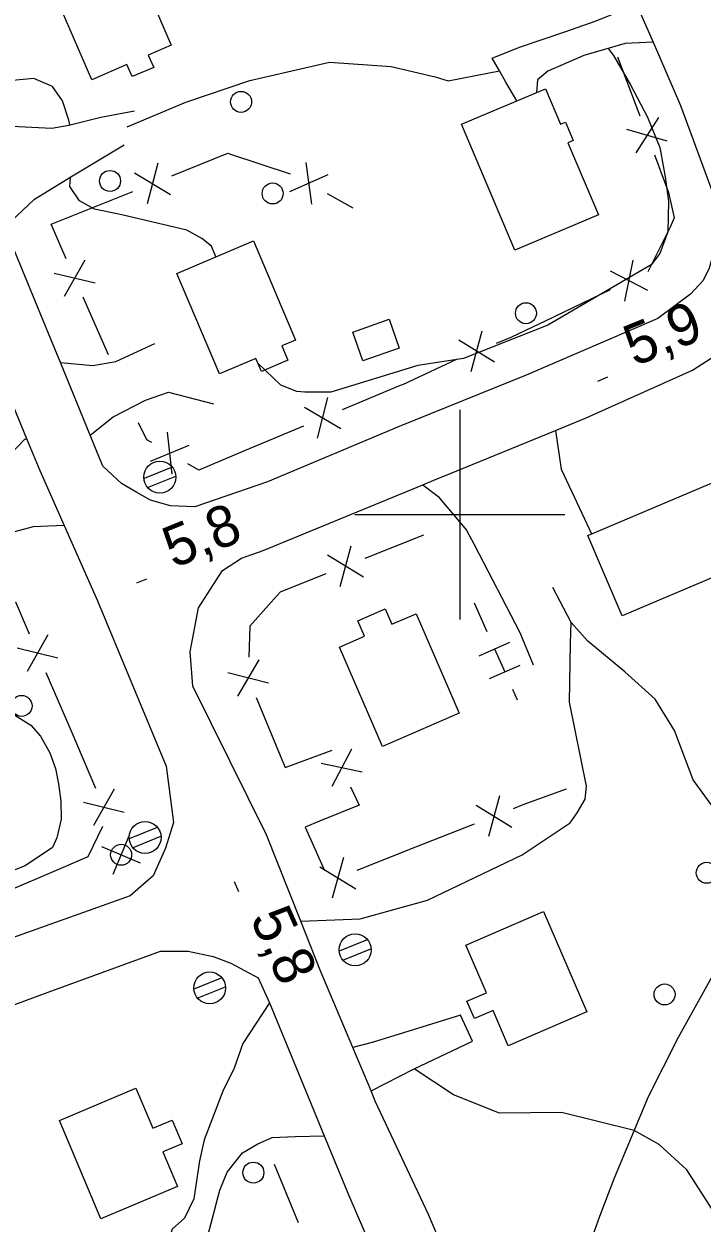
# Model space of a CAD drawing. Extents: x 362852 to 366875, y 5563573 to 5566479.
# Drawn here: x 364158.5 to 364223.1, y 5564732.5 to 5564846.8 of the extents above; entities that cross this region are included whole.
import ezdxf

# ---------------------------------------------------------------- set-up
doc = ezdxf.new("R2010")
doc.units = 0
for name, color, linetype in [('Niveau 19', 7, 'Continuous'), ('Niveau 2', 7, 'Continuous'), ('Niveau 21', 7, 'Continuous'), ('Niveau 22', 7, 'Continuous'), ('Niveau 3', 7, 'Continuous'), ('Niveau 31', 7, 'Continuous'), ('Niveau 36', 7, 'Continuous'), ('Niveau 37', 7, 'Continuous'), ('Niveau 61', 7, 'Continuous')]:
    doc.layers.add(name, color=color, linetype=linetype)

msp = doc.modelspace()

# ---------------------------------------------------------------- linework, layer by layer
at = {"layer": 'Niveau 19'}
for points in [[(364205.44, 5564839.42), (364204.39, 5564841.2), (364203.78, 5564842.29), (364203.1, 5564843.48), (364205.69, 5564844.54), (364210.02, 5564846), (364212.99, 5564847.04), (364215.14, 5564847.92), (364216.63, 5564849.16)], [(364218.42, 5564845.03), (364215.78, 5564844.88), (364211.84, 5564843.76), (364208.38, 5564842.27), (364207.41, 5564841.44), (364207.3, 5564840.21)], [(364152.13, 5564837.93), (364156.67, 5564837.06), (364161.12, 5564836.83), (364162.75, 5564837.12), (364165.8, 5564837.87), (364169, 5564838.49)], [(364156.64, 5564827.39), (364159.47, 5564830.05), (364163.11, 5564832.28), (364168.01, 5564835.22)], [(364161.94, 5564814.49), (364165.03, 5564814.2), (364167.21, 5564814.59), (364170.93, 5564816.3)], [(364164.77, 5564807.56), (364166.96, 5564809.32), (364170.06, 5564810.9), (364172.24, 5564811.67), (364176.54, 5564810.57)], [(364162.31, 5564798.95), (364159.34, 5564798.85), (364156.12, 5564797.97), (364153.67, 5564796.72), (364149.47, 5564794.19), (364146.59, 5564792.7), (364146.12, 5564793.54), (364145.48, 5564794.67), (364146.69, 5564796.98), (364146.53, 5564797.84), (364146.23, 5564799.34), (364149.87, 5564800.71), (364154.72, 5564803.87), (364157.16, 5564805.74), (364158.51, 5564807.17), (364158.71, 5564807.25)], [(364209.13, 5564808.03), (364209.68, 5564804.33), (364211.63, 5564800.15), (364212.56, 5564798.16)], [(364196.47, 5564802.84), (364197.91, 5564801.76), (364200.65, 5564798.52), (364201.37, 5564797.14), (364205.74, 5564788.78), (364207, 5564785.68)], [(364181.86, 5564753.49), (364179.34, 5564749.59), (364178.51, 5564747.26), (364177.41, 5564745.07), (364175.63, 5564740.42), (364175.19, 5564738.44), (364174.65, 5564734.8), (364173.78, 5564732.95), (364172.59, 5564731.91), (364171.97, 5564729.85), (364170.71, 5564728.96), (364170.89, 5564727.54), (364171.78, 5564726.1), (364172.84, 5564726.1), (364174.02, 5564726.71), (364175.31, 5564728.73), (364177.12, 5564735.62), (364177.84, 5564737.35), (364179.31, 5564739.19), (364180.77, 5564740.04), (364182.13, 5564740.66), (364184.33, 5564740.75), (364187.08, 5564740.82)], [(364191.55, 5564745.08), (364195.65, 5564747.19), (364201.21, 5564749.83), (364200.08, 5564752.29), (364194.63, 5564750.63), (364191.64, 5564749.71), (364189.81, 5564749.21)]]:
    msp.add_lwpolyline(points, dxfattribs=at)
at = {"layer": 'Niveau 2'}
for points in [[(364214.15, 5564844.42), (364214.64, 5564843.75), (364216.28, 5564840.94), (364217.9, 5564837.86), (364219.07, 5564834.98), (364219.58, 5564832.2), (364219.91, 5564829.85), (364219.84, 5564826.95), (364219.06, 5564824.89), (364218.25, 5564823.81), (364208.4, 5564818.04), (364200.36, 5564814.87), (364196.02, 5564814.21), (364187.71, 5564811.68), (364185.23, 5564811.66), (364184.46, 5564811.72), (364182.96, 5564812.35), (364180.75, 5564814.43), (364180.56, 5564814.89)], [(364162.85, 5564837.14), (364162.76, 5564837.58), (364162.13, 5564839.44), (364161.2, 5564840.8), (364159.4, 5564841.56), (364157.37, 5564841.35), (364156.15, 5564840.98), (364155.2, 5564839.96), (364154.48, 5564838.67), (364154.19, 5564837.53)], [(364176.75, 5564824.56), (364176.34, 5564825.58), (364175.42, 5564826.32), (364173.98, 5564827.1), (364167.79, 5564828.56), (364165.2, 5564829.11), (364163.77, 5564829.9), (364162.84, 5564831.26), (364162.91, 5564832.16)], [(364146.41, 5564777.11), (364147.11, 5564777.94), (364148.39, 5564779.09), (364150.82, 5564780.46), (364154.1, 5564781.86), (364155.22, 5564782.01), (364155.86, 5564781.96), (364157.1, 5564781.22), (364159.12, 5564779.93)], [(364159.12, 5564779.93), (364160.04, 5564778.88), (364160.93, 5564777.31), (364161.48, 5564775.8), (364161.76, 5564774.35), (364161.99, 5564772.71), (364162.01, 5564770.97), (364161.61, 5564769.19), (364161.18, 5564768.27), (364158.59, 5564766.53), (364152.47, 5564764.14), (364148.57, 5564764.41), (364147.66, 5564765.02)]]:
    msp.add_lwpolyline(points, dxfattribs=at)
at = {"layer": 'Niveau 21'}
for points in [[(364216.63, 5564849.16), (364218.42, 5564845.03), (364221.03, 5564838.99), (364224.78, 5564828.82), (364224.63, 5564826.58), (364223.77, 5564823.49), (364223.19, 5564822.32), (364221.98, 5564821.01), (364218.88, 5564818.68), (364206.32, 5564813.29), (364194.24, 5564808.41), (364181.67, 5564803.14), (364174.76, 5564800.75), (364172.42, 5564800.85), (364170.52, 5564801.38), (364169.24, 5564802.1), (364167.76, 5564802.98), (364165.97, 5564804.62), (364164.77, 5564807.56), (364161.94, 5564814.49), (364161.02, 5564816.73), (364156.64, 5564827.39)], [(364154.47, 5564817.47), (364158.71, 5564807.25), (364159.97, 5564804.22), (364162.31, 5564798.95), (364165.49, 5564791.79), (364172.02, 5564776.03), (364172.71, 5564770.65), (364171.95, 5564768.23), (364170.79, 5564765.57), (364168.58, 5564763.67), (364156.02, 5564759.21)], [(364202.8, 5564719.64), (364197.02, 5564733.32), (364191.95, 5564744.12), (364191.55, 5564745.08), (364189.81, 5564749.21), (364186.7, 5564756.59), (364184.85, 5564761.25), (364181.58, 5564769.49), (364174.55, 5564783.67), (364174.31, 5564786.93), (364175.1, 5564791.11), (364177.39, 5564794.66), (364179.21, 5564795.85), (364181.28, 5564796.57), (364196.47, 5564802.84), (364197.54, 5564803.29), (364199.19, 5564803.96), (364209.13, 5564808.03), (364212.05, 5564809.23), (364222.18, 5564813.75), (364226.74, 5564816.68)], [(364148.19, 5564749.85), (364160.77, 5564754.5), (364171.47, 5564758.39), (364174.11, 5564758.41), (364176.49, 5564757.89), (364178.18, 5564757.27), (364180.78, 5564755.85), (364181.86, 5564753.49), (364186.29, 5564742.74), (364187.08, 5564740.82), (364189.42, 5564735.12), (364193.71, 5564725.18)]]:
    msp.add_lwpolyline(points, dxfattribs=at)
at = {"layer": 'Niveau 22'}
for points in [[(364168.32, 5564836.96), (364173.9, 5564839.31), (364179.98, 5564841.36), (364187.58, 5564843.11), (364193.47, 5564842.71), (364197.67, 5564841.7), (364198.91, 5564841.33), (364203.78, 5564842.29)], [(364232.56, 5564769.27), (364228.13, 5564770.01), (364226.34, 5564770.52), (364224.48, 5564771.68), (364222.25, 5564774.74), (364220.47, 5564779.43), (364218.61, 5564782.4), (364215.74, 5564785.02), (364212.21, 5564787.94), (364210.62, 5564789.72), (364208.86, 5564793.04)], [(364206.94, 5564709.89), (364208.04, 5564715.36), (364210.03, 5564723.81), (364213.34, 5564733.15), (364214.75, 5564736.82), (364217.99, 5564744.55), (364220.85, 5564750.21), (364223.86, 5564755.63), (364228.21, 5564761.96), (364232.11, 5564768.28), (364232.56, 5564769.27), (364234.48, 5564773.48), (364235.31, 5564779.29), (364235.65, 5564787.33), (364236.12, 5564788.95), (364237.04, 5564790.75)], [(364184.85, 5564761.25), (364190.5, 5564761.5), (364196.93, 5564763.26), (364205.96, 5564767.57), (364210.51, 5564770.62), (364211.18, 5564771.58), (364211.95, 5564772.89), (364212.07, 5564774.12), (364210.47, 5564782.12), (364210.57, 5564787.76), (364210.62, 5564789.72)], [(364255.64, 5564707.29), (364252.39, 5564706.49), (364250.25, 5564706.24), (364248.51, 5564706.39), (364244.04, 5564707.61), (364242.18, 5564708.45), (364239.3, 5564710.87), (364235.19, 5564716.64), (364229.24, 5564724.72), (364226.9, 5564729.42), (364221.63, 5564737.58), (364218.99, 5564739.99), (364216.62, 5564741.3), (364209.7, 5564743.03), (364203.78, 5564742.97), (364199.39, 5564744.73), (364195.65, 5564747.19)]]:
    msp.add_lwpolyline(points, dxfattribs=at)
at = {"layer": 'Niveau 3'}
for p, q in [((364213.15, 5564812.73), (364214.11, 5564813.12)), ((364169.22, 5564793.5), (364170.18, 5564793.89)), ((364178.49, 5564765.03), (364178.92, 5564764.08))]:
    msp.add_line(p, q, dxfattribs=at)
at = {"layer": 'Niveau 31'}
for points in [[(364167.15, 5564857.11), (364172.49, 5564844.73), (364170.32, 5564843.79), (364170.83, 5564842.62), (364168.78, 5564841.74), (364168.28, 5564842.89), (364164.93, 5564841.44), (364159.58, 5564853.85), (364167.15, 5564857.11)], [(364205.25, 5564825.2), (364200.17, 5564837.19), (364208.16, 5564840.58), (364209.59, 5564837.2), (364210.07, 5564837.41), (364210.81, 5564835.65), (364210.3, 5564835.44), (364213.21, 5564828.57), (364205.25, 5564825.2)], [(364180.33, 5564826.08), (364184.36, 5564816.63), (364183.03, 5564816.07), (364183.61, 5564814.71), (364181.1, 5564813.64), (364180.57, 5564814.89), (364177.11, 5564813.42), (364173.04, 5564822.98), (364180.33, 5564826.08)], [(364189.8, 5564817.4), (364193.26, 5564818.63), (364194.24, 5564815.87), (364190.78, 5564814.64), (364189.8, 5564817.4)], [(364212.22, 5564798.01), (364224.67, 5564803.29), (364227.92, 5564795.63), (364215.47, 5564790.35), (364212.22, 5564798.01)], [(364195.86, 5564790.56), (364199.96, 5564781.08), (364192.63, 5564777.91), (364188.54, 5564787.38), (364190.92, 5564788.41), (364190.28, 5564789.89), (364192.88, 5564791.02), (364193.52, 5564789.55), (364195.86, 5564790.56)], [(364207.97, 5564762.19), (364212.1, 5564752.63), (364204.62, 5564749.39), (364203.17, 5564752.75), (364201.41, 5564751.99), (364200.69, 5564753.64), (364202.54, 5564754.44), (364200.57, 5564758.99), (364207.97, 5564762.19)], [(364165.81, 5564732.9), (364161.84, 5564742.28), (364169.14, 5564745.36), (364170.76, 5564741.53), (364172.59, 5564742.3), (364173.55, 5564740.05), (364171.71, 5564739.28), (364173.1, 5564735.98), (364165.81, 5564732.9)]]:
    msp.add_lwpolyline(points, dxfattribs=at)
at = {"layer": 'Niveau 36'}
for p, q in [((364172.59, 5564804.52), (364169.91, 5564803.43)), ((364170.25, 5564802.58), (364172.94, 5564803.67)), ((364166.96, 5564765.73), (364168.51, 5564769.4)), ((364171.16, 5564770.2), (364168.48, 5564769.11)), ((364168.82, 5564768.26), (364171.51, 5564769.35)), ((364169.57, 5564766.79), (364165.9, 5564768.34)), ((364191.19, 5564759.48), (364188.51, 5564758.39)), ((364188.85, 5564757.54), (364191.54, 5564758.63)), ((364177.33, 5564755.86), (364174.65, 5564754.77)), ((364174.99, 5564753.92), (364177.68, 5564755.01))]:
    msp.add_line(p, q, dxfattribs=at)
for centre, radius in [((364179.16, 5564839.33), 1), ((364166.67, 5564831.79), 1), ((364182.17, 5564830.6), 1), ((364206.31, 5564819.19), 1), ((364171.42, 5564803.57), 1.52), ((364158.24, 5564781.77), 1), ((364170.01, 5564769.24), 1.52), ((364167.73, 5564767.59), 1), ((364223.54, 5564765.87), 1), ((364190.03, 5564758.53), 1.52), ((364176.17, 5564754.9), 1.52), ((364219.52, 5564754.28), 1), ((364180.33, 5564737.3), 1)]:
    msp.add_circle(centre, radius, dxfattribs=at)
at = {"layer": 'Niveau 37'}
for p, q in [((364215.05, 5564843.63), (364217.16, 5564838.01)), ((364218.93, 5564837.83), (364216.78, 5564834.46)), ((364219.78, 5564835.58), (364215.94, 5564836.7)), ((364171.23, 5564833.48), (364170.2, 5564829.61)), ((364178.14, 5564834.36), (364183.83, 5564832.46)), ((364185.34, 5564833.54), (364185.88, 5564829.58)), ((364169, 5564832.58), (364172.42, 5564830.51)), ((364187.44, 5564832.37), (364183.78, 5564830.75)), ((364163.29, 5564828.57), (364168.86, 5564830.8)), ((364187.36, 5564830.59), (364189.8, 5564829.23)), ((364162.33, 5564820.8), (364164.3, 5564824.29)), ((364215.74, 5564820.33), (364216.52, 5564824.25)), ((364161.36, 5564823), (364165.26, 5564822.09)), ((364217.91, 5564821.37), (364214.36, 5564823.21)), ((364166.52, 5564815.22), (364164.11, 5564820.71)), ((364214.33, 5564821.42), (364208.92, 5564818.81)), ((364201.09, 5564813.65), (364202.14, 5564817.51)), ((364203.32, 5564814.54), (364199.91, 5564816.63)), ((364194.32, 5564812.29), (364188.79, 5564809.97)), ((364186.45, 5564807.27), (364187.43, 5564811.15)), ((364188.67, 5564808.19), (364185.22, 5564810.22)), ((364185.1, 5564808.43), (364179.56, 5564806.11)), ((364172.6, 5564803.87), (364172.15, 5564807.85)), ((364170.53, 5564805.08), (364174.22, 5564806.63)), ((364196.55, 5564798.03), (364190.97, 5564795.82)), ((364188.59, 5564793.16), (364189.64, 5564797.02)), ((364190.82, 5564794.04), (364187.41, 5564796.14)), ((364201.37, 5564791.6), (364202.59, 5564788.86)), ((364160.75, 5564788.53), (364158.76, 5564785.06)), ((364161.7, 5564786.33), (364157.81, 5564787.27)), ((364180.86, 5564786.15), (364178.82, 5564782.71)), ((364160.55, 5564784.96), (364162.92, 5564779.45)), ((364181.78, 5564783.94), (364177.9, 5564784.93)), ((364205.02, 5564783.37), (364205.48, 5564782.34)), ((364180.61, 5564782.58), (364182.9, 5564777.04)), ((364162.92, 5564779.45), (364165.29, 5564773.94)), ((364189.67, 5564777.64), (364187.8, 5564774.1)), ((364190.69, 5564775.46), (364186.78, 5564776.27)), ((364167.07, 5564773.84), (364165.08, 5564770.37)), ((364203.79, 5564773.2), (364202.73, 5564769.34)), ((364168.02, 5564771.63), (364164.13, 5564772.57)), ((364201.56, 5564772.32), (364204.96, 5564770.22)), ((364195.82, 5564768.33), (364201.4, 5564770.54)), ((364190.24, 5564766.13), (364195.82, 5564768.33)), ((364188.91, 5564767.32), (364187.85, 5564763.46)), ((364161.99, 5564766.29), (364156.48, 5564763.93)), ((364186.68, 5564766.43), (364190.09, 5564764.34)), ((364182.3, 5564738.1), (364184.61, 5564732.56))]:
    msp.add_line(p, q, dxfattribs=at)
for points in [[(364172.57, 5564832.29), (364177.91, 5564834.44), (364178.14, 5564834.36)], [(364218.56, 5564834.27), (364219.91, 5564830.68), (364220.38, 5564828.56)], [(364162.5, 5564824.38), (364161.06, 5564827.67), (364163.29, 5564828.57)], [(364220.38, 5564828.56), (364220.44, 5564828.29), (364220.06, 5564827.38), (364217.93, 5564823.15)], [(364208.92, 5564818.81), (364204.88, 5564816.87), (364203.47, 5564816.31)], [(364199.76, 5564814.82), (364194.53, 5564812.38), (364194.32, 5564812.29)], [(364170.65, 5564806.87), (364170.18, 5564807.14), (364169.4, 5564808.75)], [(364179.56, 5564806.11), (364175.12, 5564804.25), (364174.1, 5564804.85)], [(364187.25, 5564794.35), (364182.89, 5564792.62), (364182.02, 5564791.65)], [(364155.18, 5564790.68), (364157.65, 5564791.69), (364158.97, 5564788.63)], [(364182.02, 5564791.65), (364179.98, 5564789.38), (364179.89, 5564786.43)], [(364201.85, 5564786.56), (364204.78, 5564787.86)], [(364203.32, 5564787.21), (364204.29, 5564785.02)], [(364202.83, 5564784.37), (364205.75, 5564785.67)], [(364182.9, 5564777.04), (364183.37, 5564775.9), (364187.84, 5564777.56)], [(364189.59, 5564774.06), (364190.41, 5564772.32), (364186.63, 5564770.78)], [(364205.12, 5564772.01), (364206.06, 5564772.38), (364210.16, 5564773.87)], [(364186.63, 5564770.78), (364185.26, 5564770.22), (364187.11, 5564766.1)], [(364165.96, 5564770.28), (364164.54, 5564767.38), (364161.99, 5564766.29)]]:
    msp.add_lwpolyline(points, dxfattribs=at)
at = {"layer": 'Niveau 61'}
for p, q in [((364200, 5564810), (364200, 5564790)), ((364190, 5564800), (364210, 5564800))]:
    msp.add_line(p, q, dxfattribs=at)

# ---------------------------------------------------------------- texts
at = {"layer": 'Niveau 3'}
for s, rotation, p in [('5,9  ', 22.09, (364216.66, 5564814.09)), ('5,8  ', 22.09, (364172.73, 5564794.86)), ('5,8  ', 294.1146, (364179.98, 5564761.56))]:
    msp.add_text(s, height=3.93, rotation=rotation, dxfattribs=at).set_placement(p)

doc.saveas('drawing.dxf')
